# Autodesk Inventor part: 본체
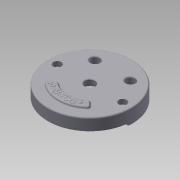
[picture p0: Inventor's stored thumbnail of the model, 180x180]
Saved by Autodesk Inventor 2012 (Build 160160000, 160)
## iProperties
Created: 2015-04
Part Number: 본체
Material: 알루미늄-6061
Document SubType Name: Modeling
Designer: Administrator
Density: 2.71 g/cm^3
Mass: 1051.94 g
Surface Area: 1006.91 cm^2
Volume: 388.169 cm^3
Author: Administrator
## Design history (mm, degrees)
sketch "스케치1"
  geometry: C1 r 95 at (0, 0); 1 further point
  constraints: 1 centre point, 1 coincident
  dimensions: "d0" = 190 diameter of C1
extrude "돌출1" new body sketch "스케치1" distance "d1" = 32; taper "d2" = 0 deg
sketch "스케치2"
  geometry: C1 r 95 at (0, 0) reference; C2 r 90 at (0, 0)
  constraints: 1 centre point, 1 coincident
  dimensions: "d3" = 180 diameter of C2
extrude "돌출2" cut sketch "스케치2" distance "d4" = 25; taper "d5" = 0 deg
sketch "스케치3"
  geometry: L1 (-40.249, 12)-(-89.196, 12); L2 (40.249, 12)-(89.196, 12); A1 r 90 centre (0, 0) between (-89.196, 12) and (89.196, 12) reference; A2 r 42 centre (0, 0) between (40.249, 12) and (-40.249, 12)
  constraints: 4 end point, 4 point on circle, 1 centre point, 1 coincident, 1 collinear
extrude "돌출3" join sketch "스케치3" distance "d8" = 7; taper "d9" = 0 deg
sketch "스케치4"
  geometry: L1 (-95, 32)-(95, 32) reference; L2 (-95, 0)-(95, 0) reference; L3 (12, 18)-(-90, 18) reference; L4 (0, 18)-(0, 8); L5 (0, 18)-(35, 18); L6 (0, 8)-(33.237, 8); L7 (35, 18)-(33.237, 8); 1 further point
  constraints: 8 end point, 2 perpendicular, 1 parallel, 1 point on line
revolve "회전1" sketch "스케치4" stored, may be unused: angle "d14" = 90 deg
sketch "스케치5"
  geometry: L1 (-89.658, -7.844)-(-94.638, -8.28); L2 (89.658, -7.844)-(94.638, -8.28); C1 r 90 at (0, 0) reference; C2 r 95 at (0, 0) reference; A1 r 90 centre (0, 0) between (-89.658, -7.844) and (89.658, -7.844); A2 r 95 centre (0, 0) between (-94.638, -8.28) and (94.638, -8.28)
  constraints: 4 end point, 4 point on circle, 2 centre point, 2 coincident, 2 concentric
extrude "돌출4" cut sketch "스케치5" distance "d17" = 5; taper "d18" = 0 deg
sketch "스케치6"
  geometry: C1 r 15 at (-40, 52); C2 r 15 at (40, 52)
  constraints: 2 centre point
extrude "돌출5" join sketch "스케치6" distance "d24" = 25; taper "d25" = 0 deg
sketch "스케치8"
  geometry: L1 (0, -19)-(0, -14); L2 (59, -19)-(59, -14); L3 (41, -19)-(41, -14); L4 (-41, -19)-(-41, -14); L5 (-59, -19)-(-59, -14); A1 r 59 centre (0, -19) between (-59, -19) and (59, -19); A2 r 41 centre (0, -19) between (-41, -19) and (41, -19); A3 r 9 centre (-50, -14) between (-41, -14) and (-59, -14); A4 r 9 centre (50, -14) between (59, -14) and (41, -14)
  constraints: 10 end point, 8 point on circle, 4 centre point, 4 tangent, 2 parallel, 1 coincident
extrude "돌출7" cut sketch "스케치8" distance "d41" = 7; taper "d42" = 0 deg
sketch "스케치9"
  geometry: C1 r 15 at (0, 0) reference; C2 r 10 at (0, 0); C3 r 15 at (80, 0) reference; C4 r 10 at (80, 0); 1 further point
  constraints: 2 centre point, 2 coincident
  dimensions: "d43" = 20 diameter of C2
extrude "돌출8" cut sketch "스케치9" distance "d45" = 50; taper "d46" = 0 deg
sketch "스케치10"
  geometry: C1 r 33.237 at (0, 0) reference; C2 r 25 at (0, 0)
  constraints: 1 centre point, 1 coincident
  dimensions: "d47" = 50 diameter of C2
extrude "돌출9" cut sketch "스케치10" distance "d48" = 15; taper "d49" = 0 deg
sketch "스케치11"
  geometry: C1 r 25 at (0, 0) reference; C2 r 11.5 at (0, 0)
  constraints: 1 centre point, 1 coincident
  dimensions: "d50" = 23 diameter of C2
extrude "돌출10" cut sketch "스케치11" distance "d51" = 20; taper "d52" = 0 deg
sketch "스케치13"
  geometry: L1 (-80, 0)-(-74, 0); L2 (-74, 8)-(-74, 13.748); L3 (-80, 0)-(-86, 0); L4 (-86, 8)-(-86, 13.748); L5 (-74, -8)-(-74, -13.748); L6 (-86, -8)-(-86, -13.748); A1 r 10 centre (-80, 0) between (-86, 8) and (-74, 8) reference; A2 r 15 centre (-80, 0) between (-86, -13.748) and (-74, -13.748) reference; 1 further point
  constraints: 12 end point, 8 point on circle, 3 perpendicular, 2 parallel, 1 horizontal
extrude "돌출12" cut sketch "스케치13" distance "d60" = 3; taper "d61" = 0 deg
sketch "스케치14"
  geometry: L1 (8, 6)-(13.748, 6); L2 (-8, 6)-(-13.748, 6); L3 (8, -6)-(13.748, -6); L4 (-8, -6)-(-13.748, -6); A1 r 10 centre (0, 0) between (-8, 6) and (8, 6) reference; A2 r 15 centre (0, 0) between (-13.748, -6) and (-13.748, 6) reference; 1 further point
  constraints: 8 end point, 8 point on circle, 2 collinear
extrude "돌출13" cut sketch "스케치14" distance "d64" = 3; taper "d65" = 0 deg
sketch "스케치15"
  geometry: L1 (-36.062, -36.062)-(-50.912, -50.912); L2 (36.062, -36.062)-(50.912, -50.912); C1 r 95 at (0, 0) reference; A1 r 51 centre (0, 0) between (-36.062, -36.062) and (36.062, -36.062); A2 r 72 centre (0, 0) between (-50.912, -50.912) and (50.912, -50.912)
  constraints: 4 end point, 4 point on circle, 2 centre point, 2 coincident
extrude "돌출14" join sketch "스케치15" distance "d70" = 5; taper "d71" = 0 deg
sketch "스케치16"
  geometry: L1 (-50.912, -50.912)-(-36.062, -36.062) reference; L2 (36.062, -36.062)-(50.912, -50.912) reference; A1 r 72 centre (0, 0) between (-50.912, -50.912) and (50.912, -50.912) reference; A2 r 68 centre (0, 0) between (-48.083, -48.083) and (48.083, -48.083)
  constraints: 2 point on circle, 2 point on line, 1 centre point, 1 coincident, 1 other
feature "엠보싱1" sketch "스케치16" dims "d75" = 0.5, "d76" = 0
fillet "모깎기1" dims "d79" = 10, "d80" = 0.3, "d81" = 3, "d83" = 1
chamfer "모따기1" distance "d95" = 1; stored, may be unused: second distance "d96" = 2, angle "d97" = 45 deg
sketch "스케치17"
  geometry: C1 r 9 at (-74, 0)
  constraints: 1 centre point
  dimensions: "d101" = 18 diameter of C1
extrude "돌출15" join sketch "스케치17" distance "d102" = 18; taper "d103" = 0 deg
sketch "스케치18"
  geometry: C1 r 9 at (0, 0) reference; C2 r 5.5 at (0, 0); 1 further point
  constraints: 1 centre point, 1 coincident
  dimensions: "d104" = 11 diameter of C2
extrude "돌출16" cut sketch "스케치18" stored distance "d105" = 18; taper "d106" = 0 deg
sketch "스케치19"
  geometry: C1 r 5.5 at (74, 0) reference; C2 r 9 at (74, 0)
  constraints: 1 centre point, 1 coincident
  dimensions: "d107" = 18 diameter of C2
extrude "돌출17" cut sketch "스케치19" distance "d108" = 11; taper "d109" = 0 deg
fillet "모깎기13" dims "d111" = 3
node "솔리드1"
fillet "모깎기2" dims "d91" = 5, "d93" = 3
fillet "모깎기3" dims "d92" = 3, "d94" = 2
mirror "대칭1"
node "투영된 루프1"
node "투영된 루프2"
node "투영된 루프4"
